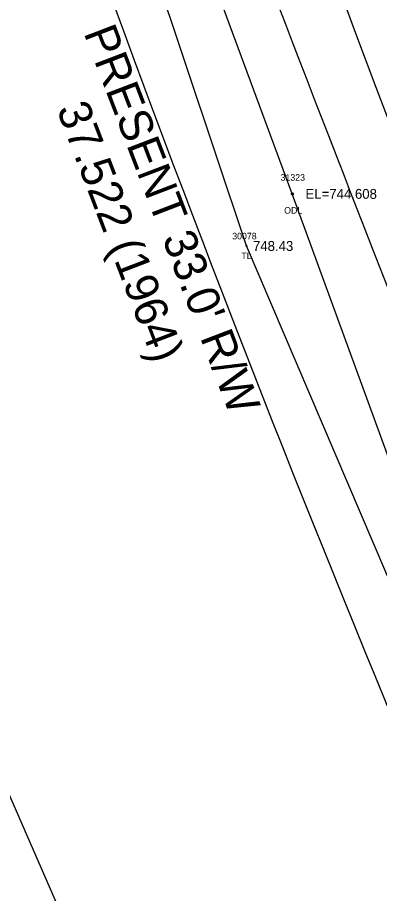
# Model space of a CAD drawing. Extents: x 1375131 to 1378678, y 999028 to 1004053.
# Drawn here: x 1376731 to 1376786.1, y 1002588 to 1002721.2 of the extents above; entities that cross this region are included whole.
import ezdxf

# ---------------------------------------------------------------- set-up
doc = ezdxf.new("R2010")
doc.units = 0
for name, color, linetype in [('RD_EX_DV_Prop', 7, 'Continuous'), ('RD_EX_H2O', 7, 'Continuous'), ('RD_EX_H2O_txCode', 7, 'Continuous'), ('RD_EX_Road', 7, 'Continuous'), ('RD_EX_RW', 7, 'Continuous'), ('RD_EX_RW_TX', 7, 'Continuous'), ('RD_EX_TX_H2O_ELEV', 7, 'Continuous'), ('RD_EX_TX_VEG_ELEV', 7, 'Continuous'), ('RD_EX_VEG', 7, 'Continuous'), ('RD_EX_VEG_txCode', 7, 'Continuous'), ('RD_HC_Cl', 7, 'Continuous'), ('RD_SMD_Locator', 7, 'Continuous')]:
    doc.layers.add(name, color=color, linetype=linetype)

msp = doc.modelspace()

# ---------------------------------------------------------------- linework, layer by layer
at = {"layer": 'RD_EX_DV_Prop'}
msp.add_lwpolyline([(1376724.42, 1002117.06), (1376637.57, 1002230.63), (1376389.38, 1002558.79), (1376664.3, 1002769.81), (1376707.09, 1002654.77), (1376824.56, 1002385.67), (1376921.89, 1002216.69), (1376947.76, 1002098.6)], dxfattribs=at)
at = {"layer": 'RD_EX_H2O'}
msp.add_lwpolyline([(1376884.04, 1002432.1), (1376867.96, 1002466.27), (1376845.47, 1002511.58), (1376827.22, 1002560.38), (1376806.48, 1002611.18), (1376788.41, 1002651.65), (1376772.82, 1002694.38), (1376753.28, 1002747.21), (1376736.65, 1002792.89), (1376719.2, 1002838.91), (1376701.08, 1002887.18), (1376684.58, 1002932.85), (1376667.2, 1002979.87)], dxfattribs=at)
at = {"layer": 'RD_EX_Road'}
msp.add_spline([(1376994.75, 1002253.91), (1376964.91, 1002306.46), (1376934.4, 1002359.99), (1376904.77, 1002415.49), (1376877.27, 1002471.51), (1376851.04, 1002526.89), (1376827.48, 1002581.62), (1376804.19, 1002637.82), (1376768.46, 1002728.84)], degree=3, dxfattribs=at)
at = {"layer": 'RD_EX_RW'}
msp.add_line((1376638.09, 1003014.36), (1376747.31, 1002718.63), dxfattribs=at)
msp.add_arc((1379404.86, 1003700.11), 2833, 200.26995, 211.13117, dxfattribs=at)
at = {"layer": 'RD_EX_VEG'}
msp.add_lwpolyline([(1376822.36, 1002383.95), (1376864.26, 1002456.06), (1376837.78, 1002513.31), (1376810.93, 1002575.39), (1376788.96, 1002632.35), (1376765.83, 1002686.46), (1376747.01, 1002742.76), (1376726.94, 1002799.92), (1376678.97, 1002911.63), (1376653.9, 1002974.89)], dxfattribs=at)
at = {"layer": 'RD_HC_Cl'}
msp.add_arc((1379404.86, 1003700.11), 2800, 200.26995, 211.13117, dxfattribs=at)
at = {"layer": 'RD_SMD_Locator'}
for centre, radius in [((1376772.82, 1002694.38), 0.15), ((1376765.83, 1002686.46), 0.075)]:
    msp.add_circle(centre, radius, dxfattribs=at)

# ---------------------------------------------------------------- texts
at = {"layer": 'RD_EX_H2O_txCode'}
for s, p in [('31323', (1376771.03, 1002696.38)), ('ODL', (1376771.58, 1002691.38))]:
    msp.add_text(s, height=1, dxfattribs=at).set_placement(p)
at = {"layer": 'RD_EX_RW_TX'}
for s, p in [("PRESENT 33.0' R/W", (1376741.01, 1002718.89)), ('37.522 (1964)', (1376736.89, 1002707.28))]:
    msp.add_text(s, height=5, rotation=290.9417, dxfattribs=at).set_placement(p)
at = {"layer": 'RD_EX_TX_H2O_ELEV'}
msp.add_text('EL=744.608', height=1.5, dxfattribs=at).set_placement((1376774.82, 1002693.63))
at = {"layer": 'RD_EX_TX_VEG_ELEV'}
msp.add_text('748.43', height=1.5, dxfattribs=at).set_placement((1376766.83, 1002685.71))
at = {"layer": 'RD_EX_VEG_txCode'}
for s, p in [('30078', (1376763.67, 1002687.46)), ('TL', (1376765.06, 1002684.46))]:
    msp.add_text(s, height=1, dxfattribs=at).set_placement(p)

doc.saveas('drawing.dxf')
